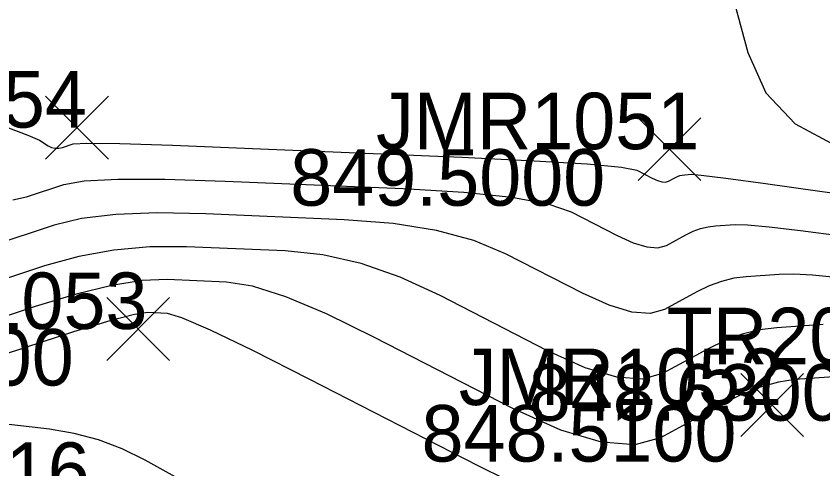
# Model space of a CAD drawing. Extents: x 1654928 to 1810050, y 486881 to 626330.
# Drawn here: x 1801337.91 to 1801355.05, y 489796.25 to 489805.87 of the extents above; entities that cross this region are included whole.
import ezdxf

# ---------------------------------------------------------------- set-up
doc = ezdxf.new("R2010")
doc.units = 0
for name, color, linetype in [('DT_X_Contour_Major', 7, 'Continuous'), ('DT_X_Contour_Minor', 7, 'Continuous'), ('SV_X_Random_Point', 7, 'Continuous'), ('SV_X_Text_Elevation', 7, 'Continuous'), ('SV_X_Text_Name', 7, 'Continuous')]:
    doc.layers.add(name, color=color, linetype=linetype)

msp = doc.modelspace()

# ---------------------------------------------------------------- linework, layer by layer
at = {"layer": 'DT_X_Contour_Major'}
msp.add_lwpolyline([(1801355.329, 489800.315), (1801354.837, 489800.363), (1801354.437, 489800.384), (1801354.127, 489800.379), (1801353.425, 489800.331), (1801353.162, 489800.298), (1801352.9, 489800.233), (1801352.64, 489800.138), (1801352.38, 489800.012), (1801351.688, 489799.635), (1801351.385, 489799.551), (1801350.993, 489799.581), (1801350.514, 489799.724), (1801349.946, 489799.982), (1801348.314, 489800.82), (1801347.64, 489801.101), (1801346.844, 489801.315), (1801345.925, 489801.462), (1801344.883, 489801.542), (1801341.94, 489801.666), (1801340.911, 489801.686), (1801340.031, 489801.652), (1801339.3, 489801.565), (1801338.718, 489801.424), (1801337.365, 489800.978)], dxfattribs=at)
at = {"layer": 'DT_X_Contour_Minor'}
for points in [[(1801352.772, 489807.642), (1801353.46, 489805.095), (1801353.84, 489804.237), (1801354.466, 489803.576), (1801355.336, 489803.111)], [(1801337.535, 489803.574), (1801338.156, 489803.341), (1801338.409, 489803.234), (1801338.592, 489803.113), (1801338.663, 489803.077), (1801338.737, 489803.059), (1801338.816, 489803.06), (1801338.898, 489803.079), (1801339.124, 489803.153), (1801339.415, 489803.168), (1801340.118, 489803.158), (1801341.233, 489803.123), (1801342.761, 489803.063), (1801347.386, 489802.868), (1801348.918, 489802.796), (1801350.048, 489802.727), (1801350.775, 489802.66), (1801351.099, 489802.596), (1801351.425, 489802.428), (1801351.539, 489802.377), (1801351.635, 489802.348), (1801351.713, 489802.342), (1801351.774, 489802.359), (1801351.912, 489802.434), (1801351.964, 489802.459), (1801352.016, 489802.478), (1801352.068, 489802.491), (1801352.121, 489802.498), (1801352.261, 489802.507), (1801352.471, 489802.488), (1801352.996, 489802.422), (1801353.834, 489802.31), (1801354.987, 489802.152), (1801358.481, 489801.669)], [(1801337.843, 489801.963), (1801338.132, 489802.028), (1801338.921, 489802.289), (1801339.357, 489802.367), (1801340.074, 489802.405), (1801341.072, 489802.404), (1801342.351, 489802.364), (1801346.134, 489802.205), (1801347.422, 489802.129), (1801348.446, 489802.021), (1801349.208, 489801.88), (1801349.706, 489801.708), (1801350.685, 489801.205), (1801351.026, 489801.05), (1801351.314, 489800.964), (1801351.549, 489800.946), (1801351.731, 489800.997), (1801352.146, 489801.223), (1801352.302, 489801.299), (1801352.458, 489801.356), (1801352.615, 489801.394), (1801352.773, 489801.414), (1801353.194, 489801.443), (1801353.454, 489801.436), (1801353.916, 489801.392), (1801354.582, 489801.313), (1801355.45, 489801.197)], [(1801355.06, 489799.315), (1801354.077, 489799.248), (1801353.709, 489799.201), (1801353.343, 489799.111), (1801352.977, 489798.978), (1801352.614, 489798.801), (1801351.646, 489798.274), (1801351.221, 489798.156), (1801350.673, 489798.197), (1801350.001, 489798.398), (1801349.206, 489798.758), (1801346.921, 489799.932), (1801346.073, 489800.321), (1801345.242, 489800.609), (1801344.428, 489800.795), (1801343.631, 489800.879), (1801341.529, 489800.967), (1801340.75, 489800.967), (1801339.988, 489800.899), (1801339.243, 489800.763), (1801338.515, 489800.56), (1801336.599, 489799.928)], [(1801355.385, 489798.209), (1801354.468, 489798.146), (1801354.109, 489798.094), (1801353.72, 489797.984), (1801353.299, 489797.816), (1801352.848, 489797.59), (1801351.603, 489796.912), (1801351.057, 489796.76), (1801350.352, 489796.814), (1801349.489, 489797.072), (1801348.466, 489797.535), (1801345.529, 489799.044), (1801344.506, 489799.542), (1801343.64, 489799.903), (1801342.931, 489800.128), (1801342.38, 489800.216), (1801341.119, 489800.269), (1801340.589, 489800.248), (1801339.944, 489800.146), (1801339.185, 489799.961), (1801338.312, 489799.696), (1801335.832, 489798.878)], [(1801348.932, 489795.722), (1801347.727, 489796.312), (1801344.136, 489798.156), (1801342.939, 489798.762), (1801342.038, 489799.197), (1801341.435, 489799.461), (1801341.128, 489799.553), (1801340.708, 489799.571), (1801340.427, 489799.529), (1801339.901, 489799.392), (1801339.128, 489799.16), (1801338.11, 489798.831), (1801335.066, 489797.828)], [(1801342.902, 489795.188), (1801340.65, 489796.433), (1801340.161, 489796.674), (1801339.659, 489796.864), (1801339.145, 489797.003), (1801338.617, 489797.09), (1801337.195, 489797.256)]]:
    msp.add_lwpolyline(points, dxfattribs=at)
at = {"layer": 'SV_X_Random_Point'}
for p, q in [((1801338.538, 489802.831), (1801339.872, 489804.166)), ((1801338.538, 489804.166), (1801339.872, 489802.831)), ((1801351.128, 489802.372), (1801352.462, 489803.707)), ((1801351.128, 489803.707), (1801352.462, 489802.372)), ((1801339.836, 489798.554), (1801341.169, 489799.889)), ((1801339.836, 489799.889), (1801341.169, 489798.554)), ((1801353.313, 489796.938), (1801354.646, 489798.273)), ((1801353.313, 489798.273), (1801354.646, 489796.938))]:
    msp.add_line(p, q, dxfattribs=at)

# ---------------------------------------------------------------- texts
at = {"layer": 'SV_X_Text_Elevation'}
for s, p in [('849.5000', (1801343.736, 489801.84)), ('848.3000', (1801332.443, 489798.021)), ('848.6300', (1801348.805, 489797.273)), ('848.5100', (1801346.526, 489796.405))]:
    msp.add_text(s, height=1.2, dxfattribs=at).set_placement(p)
at = {"layer": 'SV_X_Text_Name'}
for s, p in [('JMR1054', (1801332.545, 489803.499)), ('JMR1051', (1801345.559, 489803.04)), ('JMR1053', (1801333.833, 489799.221)), ('TR202', (1801351.734, 489798.473)), ('JMR1052', (1801347.319, 489797.605)), ('TR216', (1801334.659, 489795.613))]:
    msp.add_text(s, height=1.2, dxfattribs=at).set_placement(p)

doc.saveas('drawing.dxf')
